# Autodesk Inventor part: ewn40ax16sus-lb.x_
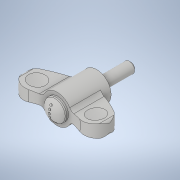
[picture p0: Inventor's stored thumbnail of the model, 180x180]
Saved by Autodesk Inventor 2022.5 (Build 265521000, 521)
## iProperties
Created: 2021-08
Part Number: ewn40ax16sus-lb.x_
Material: 一般
Document SubType Name: Modeling
Designer: ImaoCorp
Density: 1 g/cm^3
Appearance: 既定
Sending System: SOLIDWORKS 2019-2019304
MC: AMD64
MC_MODEL: Intel64 Family 6 Model 60 Stepping 3, GenuineIntel
OS: Windows_NT
FRU: Parasolid Version 31.0, build 290,  9- 1-2019
FORMAT: text
GUISE: transmit
KEY: ewn40ax16sus-lb
FILE: ewn40ax16sus-lb.x_t
DATE: Wed Aug 11 15:03:20 2021
Author: ImaoCorp
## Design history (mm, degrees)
feature "Base1"
node "ソリッド1"
